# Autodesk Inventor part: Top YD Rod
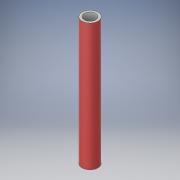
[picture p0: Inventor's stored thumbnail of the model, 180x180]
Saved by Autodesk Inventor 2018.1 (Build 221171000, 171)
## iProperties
Created: 2018-06
Part Number: Top YD Rod
Material: Generic
Document SubType Name: Modeling
Designer: Ryan
Density: 1 g/cm^3
Appearance: Default
Author: Ryan
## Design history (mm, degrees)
derived "Assembly3 Part out.iam"
sketch "Sketch1"
  geometry: L1 (-38.527, 77.015)-(136.232, 77.015); L2 (136.232, 77.015)-(136.232, -217.058); L3 (136.232, -217.058)-(-38.527, -217.058); L4 (-38.527, -217.058)-(-38.527, 77.015); 1 further point
  constraints: 8 end point, 2 parallel, 1 horizontal, 1 perpendicular
extrude "Extrusion1" cut sketch "Sketch1" distance "d1" = 25.4; taper "d2" = 0 deg
workplane "Work Plane2"
  workplane "Work Plane1"
workpoint "Work Point1"
workplane "Work Plane3"
workplane "Work Plane4"
workplane "Work Plane5"
workplane "Work Plane6"
workplane "Work Plane7"
workplane "Work Plane8"
workplane "Work Plane9"
workplane "Work Plane10"
workplane "Work Plane11"
workplane "Work Plane12"
sketch "Sketch3"
  geometry: L1 (-130.326, -239.606)-(15.915, -239.606); L2 (15.915, -239.606)-(15.915, -9.791); L3 (15.915, -9.791)-(-130.326, -9.791); L4 (-130.326, -9.791)-(-130.326, -239.606); L5 (-195.109, -187.652)-(83.263, -187.652); L6 (83.263, -187.652)-(83.263, -44.618); L7 (83.263, -44.618)-(-195.109, -44.618); L8 (-195.109, -44.618)-(-195.109, -187.652); L9 (-146.847, 71.761)-(60.979, 71.761); L10 (60.979, 71.761)-(60.979, 12.499); L11 (60.979, 12.499)-(-146.847, 12.499); L12 (-146.847, 12.499)-(-146.847, 71.761); 1 further point
  constraints: 24 end point, 6 parallel, 3 horizontal, 3 perpendicular
extrude "Extrusion2" cut sketch "Sketch3" stored distance "d10" = 273.05; taper "d11" = 0 deg
sketch "Sketch4"
  geometry: L1 (-87.53, -29.183)-(-27.13, -29.183); L2 (-27.13, -29.183)-(-27.13, 48.863); L3 (-27.13, 48.863)-(-87.53, 48.863); L4 (-87.53, 48.863)-(-87.53, -29.183); 1 further point
  constraints: 8 end point, 2 parallel, 1 horizontal, 1 perpendicular
extrude "Extrusion3" cut sketch "Sketch4" stored distance "d12" = 273.05; taper "d13" = 0 deg
sketch "Sketch5"
  geometry: L1 (-123.499, -27.147)-(14.268, -27.147); L2 (14.268, -27.147)-(14.268, 30.539); L3 (14.268, 30.539)-(-123.499, 30.539); L4 (-123.499, 30.539)-(-123.499, -27.147); 1 further point
  constraints: 8 end point, 2 parallel, 1 horizontal, 1 perpendicular
extrude "Extrusion4" cut sketch "Sketch5" distance "d14" = 273.05; taper "d15" = 0 deg
sketch "Sketch6"
  geometry: C1 r 3.429 at (0, 0); 1 further point
  constraints: 1 centre point
  dimensions: "d16" = 6.858 diameter of C1
extrude "Extrusion5" cut sketch "Sketch6" distance "d17" = 12.7; taper "d18" = 0 deg
sketch "Sketch7"
  geometry: C1 r 55.239 at (-10.83, -19.002); 1 further point
  constraints: 1 centre point
extrude "Extrusion6" cut sketch "Sketch7" extent not by distance; stored distance "d19" = 0; taper "d20" = 0 deg
sketch "Sketch8"
  geometry: C1 r 4.763 at (0, 0) reference; C2 r 3.429 at (0, 0); 1 further point
  constraints: 1 centre point, 1 coincident
  dimensions: "d21" = 6.858 diameter of C2
extrude "Extrusion7" cut sketch "Sketch8" distance "d22" = 15.875; taper "d23" = 0 deg
body "Solid1"
node "Rov v4.2.ipt:1" dims "d0" = 10
node "Motor mount.ipt:1" dims "d0" = 10
node "Motor mount.ipt:2" dims "d0" = 10
node "Motor mount_MIR2.ipt:1" dims "d0" = 10
other parameters: "d3" = 6.35, "d4" = 12.7, "d5" = -12.7, "d6" = 12.7, "d7" = -12.7, "d8" = 6.35, "d9" = -6.35
